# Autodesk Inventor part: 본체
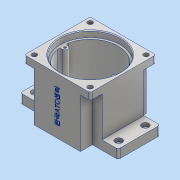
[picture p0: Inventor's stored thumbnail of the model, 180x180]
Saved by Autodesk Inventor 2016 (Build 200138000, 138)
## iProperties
Created: 2020-08
Part Number: 본체
Material: 알루미늄 6061
Document SubType Name: Modeling
Designer: User
Density: 2.7 g/cm^3
Appearance: 알루미늄 - 평지
Mass: 876.351 g
Surface Area: 793.93 cm^2
Volume: 324.574 cm^3
Author: User
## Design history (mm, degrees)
sketch "스케치6"
  geometry: L1 (-70, 30)-(70, 30); L2 (70, 30)-(70, -30); L3 (70, -30)-(-70, -30); L4 (-70, -30)-(-70, 30); L5 (-70, 30)-(70, -30); L6 (70, 30)-(-70, -30); L7 (-33, 47)-(33, 47); L8 (33, 47)-(33, -47); L9 (33, -47)-(-33, -47); L10 (-33, -47)-(-33, 47); L11 (-33, 47)-(33, -47); L12 (33, 47)-(-33, -47); 1 further point
  constraints: 24 end point, 4 midpoint, 4 parallel, 2 horizontal, 2 perpendicular
  dimensions: "d14" = 140 distance of L2.end L3.end; "d15" = 60 distance of L1.end L2.end; "d16" = 66 distance of L8.end L9.end; "d17" = 94 distance of L7.end L8.end
extrude "돌출4" new body sketch "스케치6" distance "d18" = 13; taper "d19" = 0 deg
sketch "스케치8"
  geometry: L1 (-47, 47)-(47, 47); L2 (47, 47)-(47, -47); L3 (47, -47)-(-47, -47); L4 (-47, -47)-(-47, 47); L5 (-47, 47)-(47, -47); L6 (47, 47)-(-47, -47); 1 further point
  constraints: 12 end point, 2 midpoint, 2 parallel, 1 horizontal, 1 perpendicular
  dimensions: "d22" = 94 distance of L2.end L3.end; "d23" = 94 distance of L1.end L2.end
extrude "돌출5" join sketch "스케치8" distance "d24" = 67; taper "d25" = 0 deg
sketch "스케치10"
  geometry: L1 (33, -30)-(33, -47) reference; L2 (33, -47)-(47, -47) reference; L3 (47, -47)-(47, -30) reference; L4 (47, -30)-(33, -30) reference; L5 (-33, -47)-(-33, -30) reference; L6 (-33, -30)-(-47, -30) reference; L7 (-47, -30)-(-47, -47) reference; L8 (-47, -47)-(-33, -47) reference; L9 (-47, 47)-(47, 47) reference; L10 (33, 30)-(47, 30) reference; L11 (47, 30)-(47, 47) reference; L12 (47, 47)-(33, 47) reference; L13 (33, 47)-(33, 30) reference; L14 (-47, 30)-(-33, 30) reference; L15 (-33, 30)-(-33, 47) reference; L16 (-33, 47)-(-47, 47) reference; L17 (-47, 47)-(-47, 30) reference; 1 further point
extrude "돌출6" cut sketch "스케치10" distance "d26" = 57; taper "d27" = 0 deg
sketch "스케치11"
  geometry: C1 r 27.5 at (0, -11); 1 further point
  constraints: 1 centre point, 1 vertical alignment
  dimensions: "d28" = 55 diameter of C1; "d29" = 11 distance of point (0, 0) C1.centre
extrude "돌출7" join sketch "스케치11" distance "d30" = 7; taper "d31" = 0 deg
sketch "스케치12"
  geometry: C1 r 27.5 at (0, 0) reference; C2 r 16 at (0, 0); 1 further point
  constraints: 1 centre point, 1 coincident
  dimensions: "d32" = 32 diameter of C2
sketch "스케치13"
  geometry: C1 r 43 at (0, 0); 1 further point
  constraints: 1 centre point, 1 coincident
  dimensions: "d33" = 86 diameter of C1
extrude "돌출8" cut sketch "스케치13" distance "d34" = 9; taper "d35" = 0 deg
sketch "스케치14"
  geometry: C1 r 40 at (0, 0); 1 further point
  constraints: 1 centre point, 1 coincident
  dimensions: "d36" = 80 diameter of C1
extrude "돌출9" cut sketch "스케치14" distance "d37" = 62; taper "d38" = 0 deg
extrude "돌출10" cut sketch "스케치12" distance "d39" = 8.3; taper "d40" = 0 deg
sketch "스케치15"
  geometry: C1 r 16 at (0, -11) reference; C2 r 21 at (0, -11); C3 r 15 at (0, 20); 1 further point
  constraints: 2 centre point, 1 coincident, 1 vertical alignment
  dimensions: "d41" = 42 diameter of C2; "d42" = 30 diameter of C3; "d43" = 20 distance of C3.centre point (0, 0)
extrude "돌출11" join sketch "스케치15" distance "d45" = 7; taper "d46" = 0 deg
sketch "스케치18"
  geometry: C1 r 15 at (0, 0) reference; C2 r 21 at (0, 31) reference; C3 r 11 at (0, 0); 1 further point
  constraints: 1 centre point, 1 coincident
  dimensions: "d47" = 22 diameter of C3
extrude "돌출12" cut sketch "스케치18" distance "d48" = 7; taper "d49" = 0 deg
sketch "스케치21"
  geometry: C1 r 16 at (0, 0) reference; C2 r 12.5 at (0, 0); 1 further point
  constraints: 1 centre point, 1 coincident
  dimensions: "d51" = 25 diameter of C2
  node "투영된 루프11"
sketch "스케치22"
  geometry: C1 r 17.5 at (0, -11); A1 r 21 centre (0, -11) between (-8.978, 7.984) and (8.978, 7.984) reference; 1 further point
  constraints: 1 centre point, 1 coincident
  dimensions: "d52" = 35 diameter of C1
extrude "돌출13" cut sketch "스케치22" distance "d53" = 10; taper "d54" = 0 deg
extrude "돌출14" cut sketch "스케치21" distance "d55" = 100; taper "d56" = 0 deg
sketch "스케치23"
  geometry: C1 r 11 at (0, 0) reference; C2 r 9.5 at (0, 0); 1 further point
  constraints: 1 centre point, 1 coincident
  dimensions: "d57" = 19 diameter of C2
extrude "돌출15" cut sketch "스케치23" distance "d58" = 3; taper "d59" = 0 deg
sketch "스케치25"
  geometry: A1 r 4 centre (-36, 0) between (-36.19, -3.995) and (-36.19, 3.995); A2 r 36 centre (0, 0) between (-34.718, 9.52) and (-35.772, -4.045); A3 r 3 centre (-36.333, -6.992) between (-35.772, -4.045) and (-39.279, -7.559); A4 r 40 centre (0, 0) between (-39.279, -7.559) and (-39.279, 7.559) reference; A5 r 3 centre (-36.333, 6.992) between (-39.279, 7.559) and (-35.772, 4.045); A6 r 40 centre (0, 0) between (-39.279, 7.559) and (-39.279, -7.559); 1 further point
  constraints: 16 point on circle, 5 centre point, 4 tangent, 1 coincident, 1 horizontal alignment
  dimensions: "d60" = 8 diameter of A1; "d61" = 72 diameter of A2; "d62" = 6 diameter of A3; "d63" = 6 diameter of A5
extrude "돌출16" join sketch "스케치25" stored distance "d64" = 57; taper "d65" = 0 deg
hole "구멍1" diameter "d68" = 3.242; stored, may be unused: countersink angle "d72" = 90 deg, drill point angle "d74" = 118 deg; dims "d66" = 10, "d67" = 10, "d69" = 7, "d70" = 4, "d71" = 2, "d73" = 9
sketch "스케치26"
  geometry: C1 r 3.5 at (-40, 40); 1 further point
  constraints: 1 centre point
  dimensions: "d75" = 7 diameter of C1; "d76" = 40 horizontal distance of C1.centre point (0, 0); "d77" = 40 horizontal distance of point (0, 0) C1.centre
extrude "돌출17" cut sketch "스케치26" distance "d78" = 17.75; taper "d79" = 0 deg
sketch "스케치28"
  geometry: 2 further points
  dimensions: "d86" = 19 vertical distance of point (0, 0) point (-60, 19); "d87" = 60 horizontal distance of point (-60, 19) point (0, 0)
hole "구멍2" sketch "스케치28" at (-60, 19) diameter "d88" = 4.5; stored, may be unused: countersink angle "d92" = 90 deg, drill point angle "d94" = 118 deg; dims "d89" = 20, "d90" = 10, "d91" = 5, "d93" = 53.05
sketch "스케치29"
  geometry: L1 (-14, 80)-(80, 80) reference; L2 (66, 0)-(0, 0) reference; 3 further points
  constraints: 1 midpoint, 1 vertical alignment, 1 other
  dimensions: "d101" = 40 distance from line of L1 point (33, 40)
chamfer "모따기1" distance "d102" = 0.8; stored, may be unused: second distance "d103" = 2, angle "d104" = 30 deg
fillet "모깎기1" dims "d105" = 3
chamfer "모따기2" distance "d106" = 1; stored, may be unused: second distance "d107" = 2, angle "d108" = 30 deg
feature "엠보싱1" dims "d24" = 67, "d25" = 0, "d109" = 0.5, "d110" = 0
fillet "모깎기2" dims "d111" = 3
node "솔리드2"
mirror "대칭1"
pattern_linear "직사각형 패턴1" dims "d82" = 80
pattern_linear "직사각형 패턴2" dims "d97" = 38
node "투영된 루프5"
node "투영된 루프6"
node "투영된 루프7"
node "투영된 루프8"
node "투영된 루프12"
